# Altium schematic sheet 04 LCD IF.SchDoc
size 299 x 210 mm
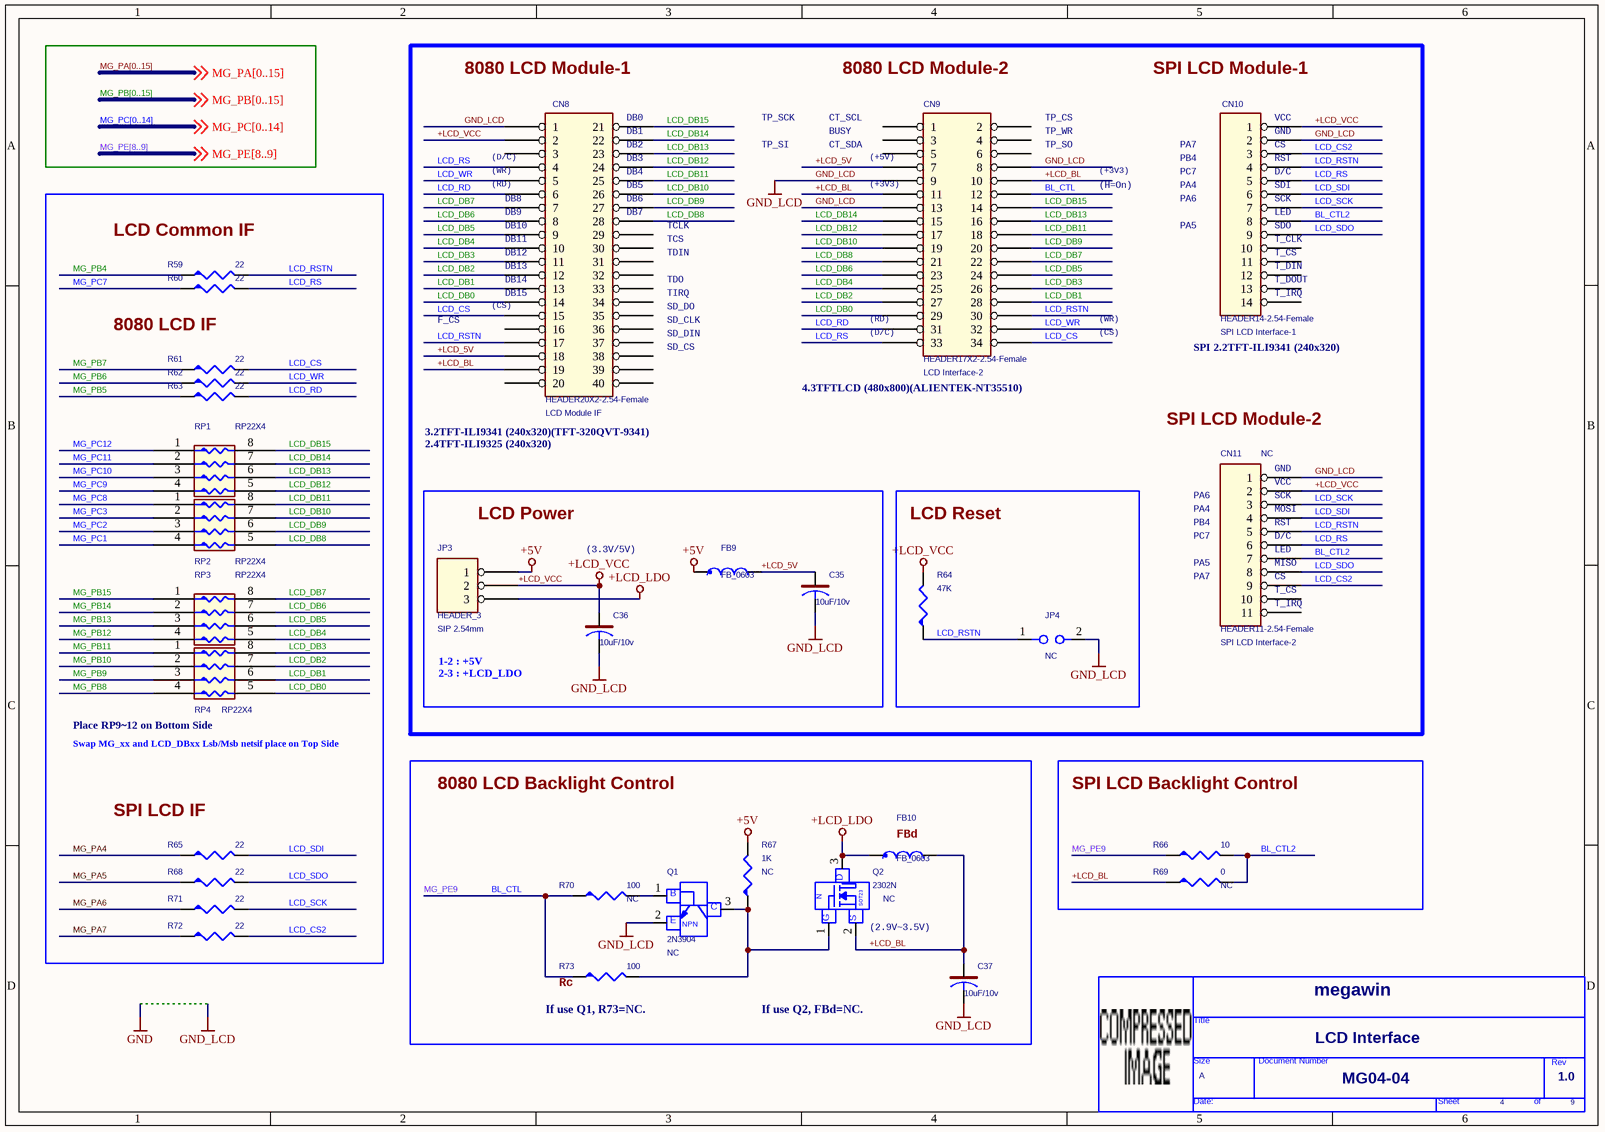
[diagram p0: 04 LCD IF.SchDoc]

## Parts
*  OrgName: megawin  Doc: MG04-04  RevCode: 1.0  Title: LCD Interface  Page Size: A  Page Number: 4  Page Count: 9  (hidden comment: TitleBlock_MegaWin)  (graphical)
C35  10uF/10v  [C-0805]
C36  10uF/10v  [C-0805]
C37  10uF/10v  [C-0805]
CN8  HEADER20X2-2.54-Female  Function: LCD Module IF  [HD20X2A-P2.54]
CN9  HEADER17X2-2.54-Female  Function: LCD Interface-2  [HD17X2-P2.54]
CN10  HEADER14-2.54-Female  Function: SPI LCD Interface-1  [SIP14-P2.54-SPI_LCD]
CN11  HEADER11-2.54-Female  Function: SPI LCD Interface-2  Assembly: NC  [SIP11-P2.54-SPI_LCD]
FB9  FB_0603  [L-0603]
FB10  FB_0603  [L-0603]
JP3  HEADER_3  Package: SIP 2.54mm  [SIP3-P2.54]
JP4  Assembly: NC  [SIP2-P2.54-JUMPER]  (hidden comment: JUMPER)
Q1  2N3904  Assembly: NC  [SOT-23]
Q2  2302N  Assembly: NC  [SOT-23]
R59  22  [R-0603]
R60  22  [R-0603]
R61  22  [R-0603]
R62  22  [R-0603]
R63  22  [R-0603]
R64  47K  [R-0603]
R65  22  [R-0603]
R66  10  [R-0603]
R67  1K  Assembly: NC  [R-0603]
R68  22  [R-0603]
R69  0  Assembly: NC  [R-0603]
R70  100  Assembly: NC  [R-0603]
R71  22  [R-0603]
R72  22  [R-0603]
R73  100  [R-0603]
RP1  RP22X4  [RP-0603]
RP2  RP22X4  [RP-0603]
RP3  RP22X4  [RP-0603]
RP4  RP22X4  [RP-0603]

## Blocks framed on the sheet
LCD Power: C35 C36 FB9 JP3
LCD Reset: JP4 R64
8080 LCD Backlight Control: C37 FB10 Q1 Q2 R67 R70 R73
SPI LCD Backlight Control: R66 R69

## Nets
+5V: FB9.1 JP3.1 R67.2
+LCD_LDO: FB10.1 JP3.3 Q2.3(D)
+LCD_VCC: C36.1 CN8.2 CN10.1 CN11.2 JP3.2 R64.2
GND_LCD: C35.2 C36.2 C37.2 CN8.1 CN9.8 CN9.9 CN9.13 CN10.2 CN11.1 JP4.2 Q1.2(E)
+LCD_5V: C35.1 CN8.18 CN9.7 FB9.2
+LCD_BL: C37.1 CN8.19 CN9.10 CN9.11 FB10.2 Q2.2(S) R69.1
BL_CTL: CN9.12 R66.1 R70.1 R73.1  [also labelled MG_PE9]
BL_CTL2: CN10.8 CN11.7 R66.2 R69.2
LCD_CS: CN8.15 CN9.34 R61.2
LCD_CS2: CN10.3 CN11.9 R72.2
LCD_DB0: CN8.14 CN9.29 RP4.5
LCD_DB1: CN8.13 CN9.28 RP4.6
LCD_DB2: CN8.12 CN9.27 RP4.7
LCD_DB3: CN8.11 CN9.26 RP4.8
LCD_DB4: CN8.10 CN9.25 RP3.5
LCD_DB5: CN8.9 CN9.24 RP3.6
LCD_DB6: CN8.8 CN9.23 RP3.7
LCD_DB7: CN8.7 CN9.22 RP3.8
LCD_DB8: CN8.28 CN9.21 RP2.5
LCD_DB9: CN8.27 CN9.20 RP2.6
LCD_DB10: CN8.26 CN9.19 RP2.7
LCD_DB11: CN8.25 CN9.18 RP2.8
LCD_DB12: CN8.24 CN9.17 RP1.5
LCD_DB13: CN8.23 CN9.16 RP1.6
LCD_DB14: CN8.22 CN9.15 RP1.7
LCD_DB15: CN8.21 CN9.14 RP1.8
LCD_RD: CN8.6 CN9.31 R63.2
LCD_RS: CN8.4 CN9.33 CN10.5 CN11.6 R60.2
LCD_RSTN: CN8.17 CN9.30 CN10.4 CN11.5 JP4.1 R59.2 R64.1
LCD_SCK: CN10.7 CN11.3 R71.2
LCD_SDI: CN10.6 CN11.4 R65.2
LCD_SDO: CN10.9 CN11.8 R68.2
LCD_WR: CN8.5 CN9.32 R62.2
MG_PA4: R65.1
MG_PA5: R68.1
MG_PA6: R71.1
MG_PA7: R72.1
MG_PB4: R59.1
MG_PB5: R63.1
MG_PB6: R62.1
MG_PB7: R61.1
MG_PB8: RP4.4
MG_PB9: RP4.3
MG_PB10: RP4.2
MG_PB11: RP4.1
MG_PB12: RP3.4
MG_PB13: RP3.3
MG_PB14: RP3.2
MG_PB15: RP3.1
MG_PC1: RP2.4
MG_PC2: RP2.3
MG_PC3: RP2.2
MG_PC7: R60.1
MG_PC8: RP2.1
MG_PC9: RP1.4
MG_PC10: RP1.3
MG_PC11: RP1.2
MG_PC12: RP1.1
NetQ1_1: Q1.1(B) R70.2
NetQ1_3: Q1.3(C) Q2.1(G) R67.1 R73.2

Not connected (* = marked no-connect by the designer): CN8 3 16 20 29 30 31 32 33 34 35 36 37 38 39 40; CN9 1 2 3 4 5 6; CN10 10 11 12 13 14; CN11 10 11

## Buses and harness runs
bus MG_PA[0..15]
bus MG_PB[0..15]
bus MG_PC[0..14]
bus MG_PE[8..9]

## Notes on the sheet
- (near CN8) 8080 LCD Module-1
- (near CN9) 8080 LCD Module-2
- (near CN10) SPI LCD Module-1
- (near CN8) DB0
- (near CN8) DB1
- TP_SCK
- BUSY
- CT_SCL
- TP_CS
- TP_WR
- (near CN10) VCC
- (near CN10) GND
- (near CN8) (D/C)
- (near CN8) (WR)
- (near CN8) (RD)
- (near CN8) DB8
- (near CN8) DB4
- (near CN8) DB5
- (near CN8) DB6
- (near CN8) DB2
- (near CN8) DB3
- TP_SI
- CT_SDA
- (near CN9) (+3V3)
- (near CN9) (+5V)
- TP_SO
- (H=On)
- (+3V3)
- PB4
- PC7
- PA7
- PA4
- PA6
- (near CN10) CS
- (near CN10) RST
- (near CN10) D/C
- (near CN10) SDI
- (near CN10) SCK
- LCD Common IF
- (near CN8) DB9
- (near CN8) DB10
- (near CN8) DB11
- (near CN8) DB12
- (near CN8) DB13
- (near CN8) DB7
- TCLK
- TCS
- TDIN
- PA5
- (near CN10) LED
- (near CN10) SDO
- (near CN10) T_CLK
- (near CN10) T_CS
- (near CN10) T_DIN
- 8080 LCD IF
- F_CS
- (near CN8) (CS)
- (near CN8) DB14
- (near CN8) DB15
- TDO
- TIRQ
- SD_DO
- SD_CLK
- SD_DIN
- (near CN9) (D/C)
- (near CN9) (RD)
- (WR)
- (CS)
- (near CN10) T_DOUT
- (near CN10) T_IRQ
- SD_CS
- (near CN9) 4.3TFTLCD (480x800)(ALIENTEK-NT35510)
- (near CN10) SPI 2.2TFT-ILI9341 (240x320)
- (near CN8) 3.2TFT-ILI9341 (240x320)(TFT-320QVT-9341)
  2.4TFT-ILI9325 (240x320)
- (near CN11) SPI LCD Module-2
- (near CN11) GND
- (near CN11) PA6
- (near CN11) PB4
- (near CN11) PC7
- (near CN11) PA4
- (near CN11) VCC
- (near CN11) SCK
- (near CN11) MOSI
- (near CN11) RST
- (near CN11) D/C
- (3.3V/5V)
- (near CN11) PA7
- (near CN11) PA5
- (near CN11) MISO
- (near CN11) LED
- (near CN11) T_IRQ
- (near CN11) T_CS
- (near CN11) CS
- (near RP4) Place RP9
  2 on Bottom Side
- (near RP4) Swap MG_xx and LCD_DBxx Lsb/Msb netsif place on Top Side
- 1-2 : +5V
  2-3 : +LCD_LDO
- (near R65) SPI LCD IF
- (near FB10) FBd
- (near Q2) (2.9V~3.5V)
- (near R73) If use Q1, R73=NC.
- (near R73) Rc
- If use Q2, FBd=NC.

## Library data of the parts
C35-C37 = CAP-POL
CN8 = HEADER20X2A
CN9 = HEADER17X2
CN10 = HEADER14
CN11 = HEADER11
FB9 FB10 = FB2
JP3 = HEADER3: 2ND PART FIELD: Pitch 2.54mm
Q1 = TRN-NPN-2N3904
Q2 = MOS-N-SOT23
R59-R63 R65 R66 R68 R69 R71 R72 = R: 2ND PART FIELD: SMD_0805
R64 R67 R70 R73 = R
RP1-RP4 = RP4-SMD2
